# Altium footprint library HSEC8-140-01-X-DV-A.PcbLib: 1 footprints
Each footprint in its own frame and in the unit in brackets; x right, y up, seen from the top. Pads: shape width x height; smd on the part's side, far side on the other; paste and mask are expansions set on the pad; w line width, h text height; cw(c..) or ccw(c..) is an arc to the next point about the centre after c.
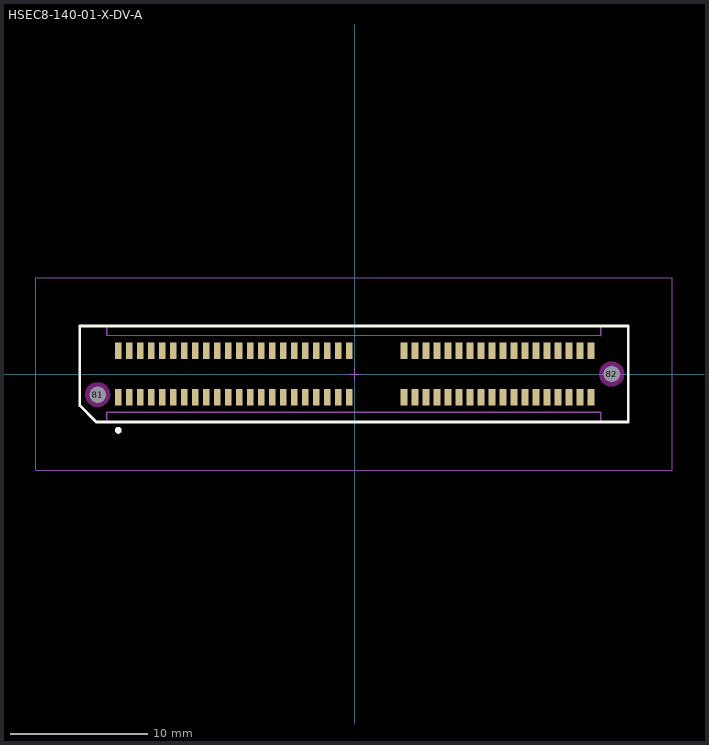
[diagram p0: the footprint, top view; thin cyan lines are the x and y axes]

## HSEC8-140-01-X-DV-A [mm] "0.80mm pitch, 80 pin, hi-speed micro edge card; w/alignment pins"
height 7.98
pads (82):
  rect 0.5x1.2 smd mask+0: 1(-17.2,-1.7) 2(-17.2,1.7) 3(-16.4,-1.7) 4(-16.4,1.7) 5(-15.6,-1.7) 6(-15.6,1.7) 7(-14.8,-1.7) 8(-14.8,1.7) 9(-14,-1.7) 10(-14,1.7) 11(-13.2,-1.7) 12(-13.2,1.7) 13(-12.4,-1.7) 14(-12.4,1.7) 15(-11.6,-1.7) 16(-11.6,1.7) 17(-10.8,-1.7) 18(-10.8,1.7) 19(-10,-1.7) 20(-10,1.7) 21(-9.2,-1.7) 22(-9.2,1.7) 23(-8.4,-1.7) 24(-8.4,1.7) 25(-7.6,-1.7) 26(-7.6,1.7) 27(-6.8,-1.7) 28(-6.8,1.7) 29(-6,-1.7) 30(-6,1.7) 31(-5.2,-1.7) 32(-5.2,1.7) 33(-4.4,-1.7) 34(-4.4,1.7) 35(-3.6,-1.7) 36(-3.6,1.7) 37(-2.8,-1.7) 38(-2.8,1.7) 39(-2,-1.7) 40(-2,1.7) 41(-1.2,-1.7) 42(-1.2,1.7) 43(-0.4,-1.7) 44(-0.4,1.7) 45(3.6,-1.7) 46(3.6,1.7) 47(4.4,-1.7) 48(4.4,1.7) 49(5.2,-1.7) 50(5.2,1.7) 51(6,-1.7) 52(6,1.7) 53(6.8,-1.7) 54(6.8,1.7) 55(7.6,-1.7) 56(7.6,1.7) 57(8.4,-1.7) 58(8.4,1.7) 59(9.2,-1.7) 60(9.2,1.7) 61(10,-1.7) 62(10,1.7) 63(10.8,-1.7) 64(10.8,1.7) 65(11.6,-1.7) 66(11.6,1.7) 67(12.4,-1.7) 68(12.4,1.7) 69(13.2,-1.7) 70(13.2,1.7) 71(14,-1.7) 72(14,1.7) 73(14.8,-1.7) 74(14.8,1.7) 75(15.6,-1.7) 76(15.6,1.7) 77(16.4,-1.7) 78(16.4,1.7) 79(17.2,-1.7) 80(17.2,1.7)
  round 1 hole 1.2 unplated mask+0: 81(-18.7,-1.5) 82(18.7,0)
Top Overlay:
  circle w0.25: c-17.2,-4.1 r0.125
  lines w0.2: -20,-2.3 -18.8,-3.5 19.9,-3.5 19.9,3.5 -20,3.5 -20,-2.3
Keep-Out Layer:
  pour cut-out: -17.792,-1.5 -17.823,-1.265 -17.914,-1.046 -18.058,-0.858 -18.246,-0.714 -18.465,-0.623 -18.7,-0.592 -18.935,-0.623 -19.154,-0.714 -19.342,-0.858 -19.486,-1.046 -19.577,-1.265 -19.608,-1.5 -19.577,-1.735 -19.486,-1.954 -19.342,-2.142 -19.154,-2.286 -18.935,-2.377 -18.7,-2.408 -18.465,-2.377 -18.246,-2.286 -18.058,-2.142 -17.914,-1.954 -17.823,-1.735
  pour cut-out: 19.608,0 19.577,0.235 19.486,0.454 19.342,0.642 19.154,0.786 18.935,0.877 18.7,0.908 18.465,0.877 18.246,0.786 18.058,0.642 17.914,0.454 17.823,0.235 17.792,0 17.823,-0.235 17.914,-0.454 18.058,-0.642 18.246,-0.786 18.465,-0.877 18.7,-0.908 18.935,-0.877 19.154,-0.786 19.342,-0.642 19.486,-0.454 19.577,-0.235
Mechanical 12:
  lines w0.001: -20,-2.3 -18.8,-3.5 19.9,-3.5 19.9,3.5 -20,3.5 -20,-2.3
Mechanical 13:
  lines w0.1: -20,-2.3 -18.8,-3.5 -18.05,-3.5 -18.05,-2.8 17.9,-2.8 17.9,-3.5 19.9,-3.5 19.9,3.5 17.9,3.5 17.9,2.8 -18.05,2.806 -18.05,3.5 -20,3.5 -20,-2.3
  text ".Designator" at 0.254,0.254 h1.52
Mechanical 15:
  lines w0.05: -0.5,0 0.5,0 ; 0,-0.5 0,0.5 ; -23.2,-7 23.1,-7 23.1,7 -23.2,7 -23.2,-7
